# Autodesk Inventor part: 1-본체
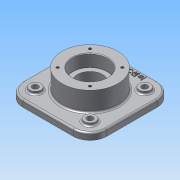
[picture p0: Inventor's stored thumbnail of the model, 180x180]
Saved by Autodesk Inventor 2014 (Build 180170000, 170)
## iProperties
Created: 2015-09
Part Number: 1-본체
Material: 알루미늄 6061
Document SubType Name: Modeling
Designer: study
Density: 2.71 g/cm^3
Appearance: 알루미늄 - 평지
Mass: 1464.68 g
Surface Area: 800.934 cm^2
Volume: 540.471 cm^3
Author: study
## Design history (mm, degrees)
sketch "스케치1"
  geometry: L1 (-75, 75)-(75, 75); L2 (75, 75)-(75, -75); L3 (75, -75)-(-75, -75); L4 (-75, -75)-(-75, 75); L5 (-75, 75)-(75, -75); L6 (75, 75)-(-75, -75); 1 further point
  constraints: 12 end point, 2 midpoint, 2 parallel, 1 horizontal, 1 perpendicular
  dimensions: "d0" = 150 distance of L1.start L1.end; "d1" = 150 distance of L1.end L2.end
extrude "돌출1" new body sketch "스케치1" distance "d2" = 12; taper "d3" = 0 deg
sketch "스케치2"
  geometry: C1 r 50 at (0, 0); 1 further point
  constraints: 1 centre point, 1 coincident
  dimensions: "d4" = 100 diameter of C1
extrude "돌출2" join sketch "스케치2" distance "d5" = 23; taper "d7" = 0 deg; dims "d6" = 47, "d8" = 0
hole "구멍1" diameter "d11" = 45; stored, may be unused: countersink angle "d15" = 90 deg, drill point angle "d17" = 118 deg; dims "d9" = 10, "d10" = 10, "d12" = 6, "d13" = 62, "d14" = 22, "d16" = 8
hole "구멍2" diameter "d20" = 45; stored, may be unused: countersink angle "d24" = 90 deg, drill point angle "d26" = 118 deg; dims "d18" = 10, "d19" = 10, "d21" = 6, "d22" = 62, "d23" = 22, "d25" = 8
fillet "모깎기1" dims "d27" = 30
sketch "스케치3"
  geometry: L1 (49, -49)-(-49, -49); L2 (-49, -49)-(-49, 49); L3 (-49, 49)-(49, 49); L4 (49, 49)-(49, -49); C1 r 50 at (0, 0) reference; C2 r 10 at (-49, 49); C3 r 10 at (49, 49); C4 r 10 at (-49, -49); C5 r 10 at (49, -49); 2 further points
  constraints: 8 end point, 5 coincident, 4 centre point, 3 equal radius, 1 midpoint, 1 vertical alignment, 9 other
  dimensions: "d28" = 98 distance of L2.end L3.end; "d29" = 20 diameter of C5
extrude "돌출3" join sketch "스케치3" distance "d30" = 5; taper "d31" = 0 deg
sketch "스케치4"
  geometry: C1 r 10 at (0, 0) reference; C2 r 10 at (-98, 0) reference; C3 r 10 at (-98, -98) reference; C4 r 10 at (0, -98) reference; 1 further point
hole "구멍3" sketch "스케치4" at (-98, 0), (0, 0), (0, -98), (-98, -98) diameter "d32" = 11; stored, may be unused: countersink angle "d36" = 90 deg, drill point angle "d38" = 118 deg; dims "d33" = 6, "d34" = 62, "d35" = 22, "d37" = 8
sketch "스케치5"
  geometry: L1 (28.991, -28.991)-(-28.991, -28.991); L2 (-28.991, -28.991)-(-28.991, 28.991); L3 (-28.991, 28.991)-(28.991, 28.991); L4 (28.991, 28.991)-(28.991, -28.991); C1 r 31 at (0, 0) reference; C2 r 50 at (0, 0) reference; 2 further points
  constraints: 8 end point, 1 coincident, 1 midpoint, 1 vertical alignment, 9 other
  dimensions: "d39" = 82 distance of L1.end L3.end
hole "구멍4" sketch "스케치5" at (28.991, 28.991) diameter "d40" = 4.917; stored, may be unused: countersink angle "d44" = 90 deg, drill point angle "d46" = 118 deg; dims "d41" = 10, "d42" = 62, "d43" = 22, "d45" = 13
node "작업 평면1"
sketch "스케치6"
  geometry: C1 r 50 at (0, 0) reference; 1 further point
  constraints: 1 vertical alignment, 1 other
  dimensions: "d50" = 65 distance of C1.centre point (0, 65)
feature "엠보싱1" sketch "스케치6" dims "d0" = 150, "d1" = 150, "d51" = 1, "d52" = 0
fillet "모깎기2" dims "d53" = 3, "d54" = 0.3
chamfer "모따기1" distance "d55" = 1; stored, may be unused: second distance "d56" = 2, angle "d57" = 45 deg
node "솔리드1"
pattern_circular "원형 패턴1" dims angle "d48" = 360 deg
mirror "대칭1"
node "투영된 루프1"
node "투영된 루프2"
node "투영된 루프3"
